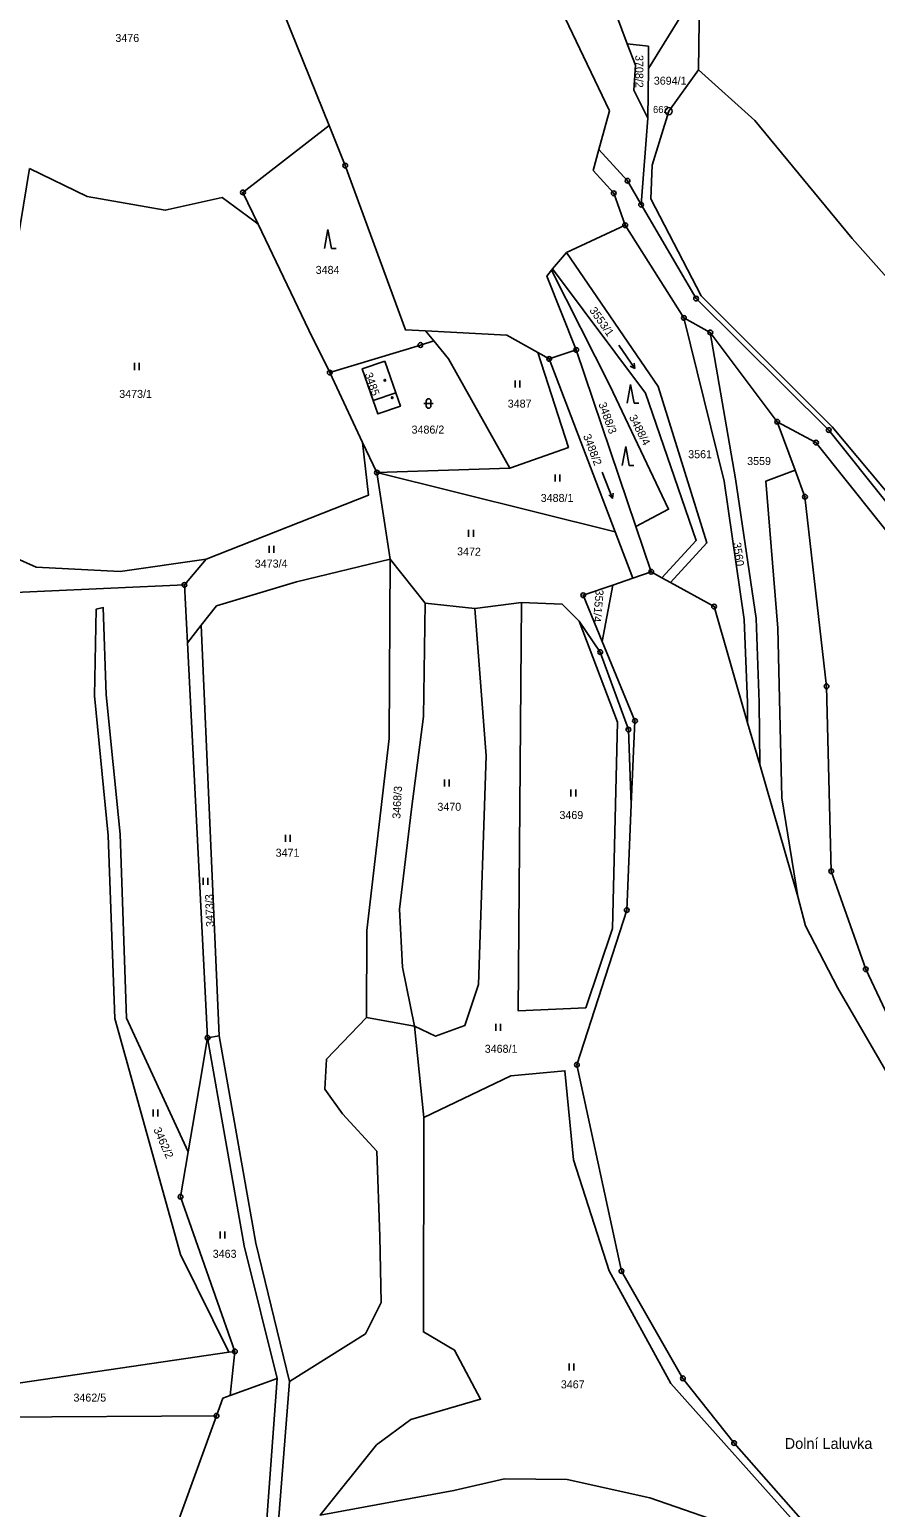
# Model space of a CAD drawing. Extents: x -644096 to -634268, y -1141430 to -1133463.
# Drawn here: x -641546.1 to -641366.3, y -1138053 to -1137739 of the extents above; entities that cross this region are included whole.
import ezdxf

# ---------------------------------------------------------------- set-up
doc = ezdxf.new("R2010")
doc.units = 0
for name, color, linetype in [('_CIVIL_CONSTRUCTION', 7, 'Continuous'), ('M_Svah_Nasyp', 7, 'Continuous'), ('M_Svah_Zarez', 7, 'Continuous'), ('svrsek_osa_sjezdy', 7, 'Continuous'), ('svrsek_osa_VRT', 7, 'Continuous'), ('svrsek_popisy_VRT', 7, 'Continuous'), ('terminal_VRT', 7, 'Continuous')]:
    doc.layers.add(name, color=color, linetype=linetype)

msp = doc.modelspace()

# ---------------------------------------------------------------- linework, layer by layer
at = {"layer": '_CIVIL_CONSTRUCTION'}
for centre, radius in [((-641410.28, -1137756.33), 0.75), ((-641410.28, -1137756.33), 0.03), ((-641479.03, -1137767.88), 0.5), ((-641479.03, -1137767.88), 0.0303), ((-641419.02, -1137771.11), 0.5), ((-641419.02, -1137771.11), 0.0303), ((-641500.77, -1137773.59), 0.5), ((-641500.77, -1137773.59), 0.0303), ((-641421.97, -1137773.78), 0.5), ((-641421.97, -1137773.78), 0.0303), ((-641416.17, -1137776.19), 0.5), ((-641416.17, -1137776.19), 0.0303), ((-641419.54, -1137780.55), 0.5), ((-641419.54, -1137780.55), 0.0303), ((-641404.46, -1137796.15), 0.5), ((-641404.46, -1137796.15), 0.0303), ((-641407.05, -1137800.25), 0.5), ((-641407.05, -1137800.25), 0.0303), ((-641401.44, -1137803.34), 0.5), ((-641401.44, -1137803.34), 0.0303), ((-641463.05, -1137806.01), 0.5), ((-641463.05, -1137806.01), 0.0303), ((-641429.94, -1137807.04), 0.5), ((-641435.67, -1137808.96), 0.5), ((-641435.67, -1137808.96), 0.0303), ((-641429.94, -1137807.04), 0.0303), ((-641482.33, -1137811.86), 0.5), ((-641482.33, -1137811.86), 0.0303), ((-641387.22, -1137822.31), 0.5), ((-641387.22, -1137822.31), 0.0303), ((-641376.27, -1137824.09), 0.5), ((-641376.27, -1137824.09), 0.0303), ((-641378.98, -1137826.73), 0.5), ((-641378.98, -1137826.73), 0.0303), ((-641472.29, -1137833.12), 0.5), ((-641472.29, -1137833.12), 0.0303), ((-641381.32, -1137838.24), 0.5), ((-641381.32, -1137838.24), 0.0303), ((-641414.01, -1137854.19), 0.5), ((-641513.21, -1137856.99), 0.5), ((-641513.21, -1137856.99), 0.0303), ((-641414.01, -1137854.19), 0.0303), ((-641428.45, -1137859.18), 0.5), ((-641428.45, -1137859.18), 0.0303), ((-641400.64, -1137861.57), 0.5), ((-641400.64, -1137861.57), 0.0303), ((-641424.83, -1137871.24), 0.5), ((-641424.83, -1137871.24), 0.0303), ((-641376.74, -1137878.53), 0.5), ((-641376.74, -1137878.53), 0.0303), ((-641417.45, -1137885.88), 0.5), ((-641418.85, -1137887.73), 0.5), ((-641418.85, -1137887.73), 0.0303), ((-641417.45, -1137885.88), 0.0303), ((-641375.73, -1137917.82), 0.5), ((-641375.73, -1137917.82), 0.0303), ((-641419.21, -1137926.07), 0.5), ((-641419.21, -1137926.07), 0.0303), ((-641368.41, -1137938.64), 0.5), ((-641368.41, -1137938.64), 0.0303), ((-641508.28, -1137953.19), 0.5), ((-641508.28, -1137953.19), 0.0303), ((-641429.79, -1137958.93), 0.5), ((-641429.79, -1137958.93), 0.0303), ((-641514.04, -1137986.99), 0.5), ((-641514.04, -1137986.99), 0.0303), ((-641420.33, -1138002.78), 0.5), ((-641420.33, -1138002.78), 0.0303), ((-641502.49, -1138019.84), 0.5), ((-641502.49, -1138019.84), 0.0303), ((-641407.28, -1138025.56), 0.5), ((-641407.28, -1138025.56), 0.0303), ((-641506.38, -1138033.52), 0.5), ((-641506.38, -1138033.52), 0.0303), ((-641396.39, -1138039.31), 0.5), ((-641396.39, -1138039.31), 0.0303)]:
    msp.add_circle(centre, radius, dxfattribs=at)
at = {"layer": 'M_Svah_Nasyp'}
msp.add_line((-641473.08, -1137817.79), (-641468.29, -1137816.14), dxfattribs=at)
at = {"layer": 'M_Svah_Zarez'}
for centre in [(-641470.61, -1137813.5), (-641469.05, -1137817.2)]:
    msp.add_circle(centre, 0.175, dxfattribs=at)
at = {"layer": 'svrsek_osa_sjezdy'}
for p, q in [((-641482.73, -1137781.48), (-641483.48, -1137785.48)), ((-641481.98, -1137785.48), (-641482.73, -1137781.48)), ((-641481.98, -1137785.48), (-641480.98, -1137785.48)), ((-641420.92, -1137806.07), (-641417.48, -1137810.99)), ((-641523.81, -1137811.32), (-641523.81, -1137809.82)), ((-641522.81, -1137811.32), (-641522.81, -1137809.82)), ((-641417.48, -1137810.99), (-641417.63, -1137809.9)), ((-641417.48, -1137810.99), (-641418.45, -1137810.47)), ((-641442.91, -1137815.04), (-641442.91, -1137813.54)), ((-641441.91, -1137815.04), (-641441.91, -1137813.54)), ((-641418.4, -1137814.39), (-641419.15, -1137818.39)), ((-641417.65, -1137818.39), (-641418.4, -1137814.39)), ((-641462.33, -1137818.44), (-641460.33, -1137818.44)), ((-641461.83, -1137817.94), (-641461.83, -1137818.94)), ((-641460.83, -1137818.94), (-641460.83, -1137817.94)), ((-641417.65, -1137818.39), (-641416.65, -1137818.39)), ((-641419.42, -1137827.6), (-641420.17, -1137831.6)), ((-641418.67, -1137831.6), (-641419.42, -1137827.6)), ((-641418.67, -1137831.6), (-641417.67, -1137831.6)), ((-641434.44, -1137835), (-641434.44, -1137833.5)), ((-641433.44, -1137835), (-641433.44, -1137833.5)), ((-641424.45, -1137833.03), (-641422.21, -1137838.59)), ((-641422.21, -1137838.59), (-641423.04, -1137837.87)), ((-641422.21, -1137838.59), (-641422.11, -1137837.5)), ((-641452.81, -1137846.75), (-641452.81, -1137845.25)), ((-641451.81, -1137846.75), (-641451.81, -1137845.25)), ((-641495.2, -1137850.18), (-641495.2, -1137848.68)), ((-641494.2, -1137850.18), (-641494.2, -1137848.68)), ((-641457.96, -1137899.84), (-641457.96, -1137898.34)), ((-641456.96, -1137899.84), (-641456.96, -1137898.34)), ((-641431.06, -1137901.95), (-641431.06, -1137900.45)), ((-641430.06, -1137901.95), (-641430.06, -1137900.45)), ((-641491.72, -1137911.6), (-641491.72, -1137910.1)), ((-641490.72, -1137911.6), (-641490.72, -1137910.1)), ((-641509.23, -1137920.71), (-641509.23, -1137919.21)), ((-641508.23, -1137920.71), (-641508.23, -1137919.21)), ((-641447.02, -1137951.76), (-641447.02, -1137950.26)), ((-641446.02, -1137951.76), (-641446.02, -1137950.26)), ((-641519.86, -1137969.95), (-641519.86, -1137968.45)), ((-641518.86, -1137969.95), (-641518.86, -1137968.45)), ((-641505.61, -1137995.88), (-641505.61, -1137994.38)), ((-641504.61, -1137995.88), (-641504.61, -1137994.38)), ((-641431.42, -1138023.92), (-641431.42, -1138022.42)), ((-641430.42, -1138023.92), (-641430.42, -1138022.42))]:
    msp.add_line(p, q, dxfattribs=at)
for centre, start, end in [((-641461.33, -1137817.94), 0, 180), ((-641461.33, -1137818.94), 180, 359.9879)]:
    msp.add_arc(centre, 0.5, start, end, dxfattribs=at)
at = {"layer": 'terminal_VRT'}
for p, q in [((-641482.45, -1137759.38), (-641495.91, -1137725.95)), ((-641403.67, -1137729.6), (-641414.58, -1137747.28)), ((-641403.97, -1137747.54), (-641403.67, -1137729.6)), ((-641414.58, -1137747.28), (-641414.72, -1137757.83)), ((-641414.72, -1137757.83), (-641416.17, -1137776.19)), ((-641419.54, -1137780.55), (-641431.98, -1137786.38)), ((-641419.54, -1137780.55), (-641407.05, -1137800.25)), ((-641431.98, -1137786.38), (-641434.95, -1137789.83)), ((-641412.55, -1137814.85), (-641431.98, -1137786.38)), ((-641434.95, -1137789.83), (-641435.18, -1137790.11)), ((-641407.05, -1137800.25), (-641401.44, -1137803.34)), ((-641460.23, -1137805.15), (-641462, -1137803.01)), ((-641401.44, -1137803.34), (-641387.22, -1137822.31)), ((-641435.67, -1137808.96), (-641438.1, -1137807.6)), ((-641429.94, -1137807.04), (-641435.67, -1137808.96)), ((-641421.65, -1137845.7), (-641435.67, -1137808.96)), ((-641417.26, -1137844.56), (-641429.94, -1137807.04)), ((-641475.35, -1137826.72), (-641482.33, -1137811.86)), ((-641383.41, -1137832.6), (-641387.22, -1137822.31)), ((-641475.35, -1137826.72), (-641472.29, -1137833.12)), ((-641472.29, -1137833.12), (-641444.08, -1137832.16)), ((-641421.65, -1137845.7), (-641472.29, -1137833.12)), ((-641472.29, -1137833.12), (-641469.47, -1137851.53)), ((-641414.01, -1137854.19), (-641417.26, -1137844.56)), ((-641417.9, -1137855.54), (-641421.65, -1137845.7)), ((-641508.61, -1137851.53), (-641513.21, -1137856.99)), ((-641462.06, -1137860.84), (-641469.47, -1137851.53)), ((-641512.58, -1137869.26), (-641513.21, -1137856.99)), ((-641424.41, -1137868.99), (-641422.18, -1137857.02)), ((-641422.18, -1137857.02), (-641417.9, -1137855.54)), ((-641417.9, -1137855.54), (-641414.01, -1137854.19)), ((-641414.01, -1137854.19), (-641411.73, -1137855.45)), ((-641411.73, -1137855.45), (-641409.92, -1137856.45)), ((-641451.48, -1137861.98), (-641462.06, -1137860.84)), ((-641441.58, -1137860.7), (-641451.48, -1137861.98)), ((-641509.63, -1137865.54), (-641512.58, -1137869.26)), ((-641509.63, -1137865.54), (-641505.82, -1137952.76)), ((-641508.28, -1137953.19), (-641512.58, -1137869.26)), ((-641393.51, -1137886.26), (-641390.95, -1137895.12)), ((-641390.95, -1137895.12), (-641382.86, -1137923.16)), ((-641464.35, -1137950.73), (-641474.51, -1137948.89)), ((-641462.33, -1137970.13), (-641464.35, -1137950.73)), ((-641505.82, -1137952.76), (-641508.28, -1137953.19)), ((-641503.78, -1138020.02), (-641502.49, -1138019.84)), ((-641503.48, -1138029.21), (-641502.49, -1138019.84)), ((-641493.5, -1138025.57), (-641503.48, -1138029.21)), ((-641506.38, -1138033.52), (-641595.89, -1138034.03))]:
    msp.add_line(p, q, dxfattribs=at)
for points in [[(-641425.11, -1137764.49), (-641422.86, -1137756.22), (-641456.68, -1137685.58), (-641495.74, -1137612.44), (-641501.22, -1137583.22), (-641506.04, -1137580.52), (-641511.42, -1137577.68)], [(-641419.09, -1137742.01), (-641428.9, -1137715.68), (-641445.3, -1137689.82), (-641463.81, -1137649.83), (-641469.75, -1137633.68)], [(-641414.72, -1137757.83), (-641417.69, -1137751.87), (-641417.32, -1137746.58), (-641419.09, -1137742.01)], [(-641419.09, -1137742.01), (-641414.59, -1137742.53), (-641414.58, -1137747.28)], [(-641403.97, -1137747.54), (-641410.28, -1137756.33), (-641413.83, -1137767.83), (-641414.09, -1137774.97), (-641403.42, -1137795.54), (-641375.56, -1137823.38), (-641348.59, -1137855.53), (-641324.75, -1137879.5), (-641325.44, -1137880.23)], [(-641314.16, -1137848.09), (-641339.44, -1137819.2), (-641371.31, -1137783.36), (-641392.01, -1137758.33), (-641403.97, -1137747.54)], [(-641497.56, -1137780.31), (-641500.77, -1137773.59), (-641482.45, -1137759.38)], [(-641462, -1137803.01), (-641466.23, -1137802.79), (-641479.03, -1137767.88), (-641482.45, -1137759.38)], [(-641425.11, -1137764.49), (-641426.33, -1137768.95), (-641421.97, -1137773.78), (-641419.54, -1137780.55)], [(-641416.17, -1137776.19), (-641419.02, -1137771.11), (-641425.11, -1137764.49)], [(-641546.15, -1137768.53), (-641559.05, -1137846.83), (-641544.72, -1137853.19), (-641526.86, -1137854.13), (-641508.61, -1137851.53)], [(-641497.56, -1137780.31), (-641498.49, -1137779.62), (-641505.2, -1137774.68), (-641517.3, -1137777.37), (-641533.87, -1137774.42), (-641546.15, -1137768.53)], [(-641325.44, -1137880.23), (-641350.07, -1137856.89), (-641376.27, -1137824.09), (-641404.46, -1137796.15), (-641416.17, -1137776.19)], [(-641482.33, -1137811.86), (-641486.78, -1137802.83), (-641497.56, -1137780.31)], [(-641435.18, -1137790.11), (-641436.17, -1137791.36), (-641429.94, -1137807.04)], [(-641417.26, -1137844.56), (-641410.32, -1137840.91), (-641422.79, -1137814.6), (-641435.18, -1137790.11)], [(-641411.73, -1137855.45), (-641404.43, -1137847.57), (-641415.22, -1137816.27), (-641434.95, -1137789.83)], [(-641407.05, -1137800.25), (-641398.52, -1137834.94), (-641394.22, -1137864.36), (-641393.54, -1137881.99), (-641393.51, -1137886.26)], [(-641438.1, -1137807.6), (-641444.69, -1137803.93), (-641462, -1137803.01)], [(-641401.44, -1137803.34), (-641396.06, -1137834.46), (-641391.73, -1137864.13), (-641391.04, -1137881.93), (-641390.95, -1137895.12)], [(-641482.33, -1137811.86), (-641463.05, -1137806.01), (-641460.23, -1137805.15)], [(-641444.08, -1137832.16), (-641457.08, -1137808.96), (-641460.23, -1137805.15)], [(-641470.6, -1137809.41), (-641475.41, -1137811.04), (-641473.08, -1137817.79), (-641472.1, -1137820.64), (-641467.31, -1137818.99), (-641468.29, -1137816.14), (-641470.6, -1137809.41)], [(-641444.08, -1137832.16), (-641431.59, -1137827.76), (-641438.1, -1137807.6)], [(-641409.92, -1137856.45), (-641402.15, -1137848.05), (-641412.55, -1137814.85)], [(-641387.22, -1137822.31), (-641378.98, -1137826.73), (-641352.66, -1137859.72), (-641333.71, -1137878.21), (-641324, -1137888.22)], [(-641508.61, -1137851.53), (-641474.08, -1137837.89), (-641475.35, -1137826.72)], [(-641383.41, -1137832.6), (-641389.64, -1137834.93), (-641387.1, -1137866.2), (-641386.26, -1137902.21), (-641382.86, -1137923.16)], [(-641351.26, -1137964.87), (-641363.09, -1137949.85), (-641368.41, -1137938.64), (-641375.73, -1137917.82), (-641376.74, -1137878.53), (-641381.32, -1137838.24), (-641383.41, -1137832.6)], [(-641469.47, -1137851.53), (-641489.39, -1137856.34), (-641506.38, -1137861.44), (-641509.63, -1137865.54)], [(-641469.47, -1137851.53), (-641469.68, -1137889.61), (-641474.47, -1137930.44), (-641474.51, -1137948.89)], [(-641513.21, -1137856.99), (-641560.23, -1137859.08), (-641572.97, -1137858.51)], [(-641424.41, -1137868.99), (-641428.45, -1137859.18), (-641422.18, -1137857.02)], [(-641409.92, -1137856.45), (-641400.64, -1137861.57), (-641393.51, -1137886.26)], [(-641512.41, -1137977.43), (-641525.53, -1137949.04), (-641526.9, -1137909.94), (-641529.85, -1137880.33), (-641530.47, -1137861.81), (-641531.98, -1137862.16), (-641532.34, -1137880.58), (-641529.39, -1137910.19), (-641528.03, -1137949.13), (-641514.07, -1137999.24), (-641503.78, -1138020.02)], [(-641464.35, -1137950.73), (-641466.89, -1137938.19), (-641467.53, -1137925.88), (-641464.92, -1137904.66), (-641462.43, -1137884.93), (-641462.06, -1137860.84)], [(-641451.48, -1137861.98), (-641449.1, -1137893.33), (-641450.74, -1137941.89), (-641453.61, -1137950.61), (-641459.87, -1137952.86), (-641464.35, -1137950.73)], [(-641429.34, -1137864.65), (-641421.15, -1137886.15), (-641422.23, -1137929.97), (-641427.93, -1137946.83), (-641442.3, -1137947.47), (-641441.58, -1137860.7)], [(-641429.34, -1137864.65), (-641432.96, -1137861.07), (-641441.58, -1137860.7)], [(-641418.23, -1137903.63), (-641418.85, -1137887.73), (-641424.83, -1137871.24), (-641429.34, -1137864.65)], [(-641418.23, -1137903.63), (-641417.45, -1137885.88), (-641424.41, -1137868.99)], [(-641373.85, -1138064.88), (-641396.39, -1138039.31), (-641407.28, -1138025.56), (-641420.33, -1138002.78), (-641429.79, -1137958.93), (-641419.21, -1137926.07), (-641418.23, -1137903.63)], [(-641382.86, -1137923.16), (-641381.18, -1137929.41), (-641374.33, -1137942.68), (-641355.72, -1137974.76), (-641320.69, -1137998.81), (-641248.56, -1138012.71)], [(-641474.51, -1137948.89), (-641483.04, -1137957.75), (-641483.4, -1137964.13), (-641479.62, -1137969.33), (-641472.34, -1137977.31), (-641471.66, -1137995.44), (-641471.38, -1138009.48), (-641474.72, -1138016.1), (-641490.88, -1138026.24)], [(-641512.41, -1137977.43), (-641510.08, -1137963.74), (-641508.28, -1137953.19)], [(-641493.5, -1138025.57), (-641500.51, -1137997.38), (-641508.28, -1137953.19)], [(-641490.88, -1138026.24), (-641498.06, -1137996.85), (-641505.82, -1137952.76)], [(-641373.85, -1138064.88), (-641381.96, -1138057.82), (-641409.8, -1138026.63), (-641422.93, -1138002.74), (-641430.51, -1137979.16), (-641432.33, -1137960.22), (-641443.82, -1137961.29), (-641462.33, -1137970.13)], [(-641370.69, -1138086.45), (-641384.8, -1138065.03), (-641394.24, -1138057.89), (-641414.27, -1138050.93), (-641431.86, -1138047.07), (-641445.19, -1138046.92), (-641455.94, -1138049.41), (-641484.39, -1138054.62), (-641472.41, -1138039.72), (-641465.08, -1138034.31), (-641450.28, -1138030), (-641455.8, -1138019.55), (-641462.41, -1138015.68), (-641462.33, -1137970.13)], [(-641502.49, -1138019.84), (-641514.04, -1137986.99), (-641512.41, -1137977.43)], [(-641595.89, -1138034.03), (-641556.35, -1138027.37), (-641554.85, -1138027.5), (-641503.78, -1138020.02)], [(-641378.25, -1138084.34), (-641385.85, -1138082.21), (-641419.6, -1138072.79), (-641485.59, -1138065.55), (-641493.32, -1138062.69), (-641495.98, -1138059.38), (-641493.5, -1138025.57)], [(-641378.25, -1138084.34), (-641395.46, -1138072.42), (-641485.01, -1138063.1), (-641491.8, -1138060.59), (-641493.41, -1138058.58), (-641490.88, -1138026.24)], [(-641503.48, -1138029.21), (-641505.02, -1138029.78), (-641506.38, -1138033.52)], [(-641506.38, -1138033.52), (-641514.19, -1138054.98), (-641511, -1138065.92), (-641499.25, -1138078.39), (-641497.55, -1138082.01), (-641499.97, -1138099.24)]]:
    msp.add_lwpolyline(points, dxfattribs=at)

# ---------------------------------------------------------------- texts
at = {"layer": '_CIVIL_CONSTRUCTION'}
msp.add_text('662', height=1.5, dxfattribs=at).set_placement((-641413.62, -1137756.71))
at = {"layer": 'svrsek_osa_VRT'}
for s, p in [('3476', (-641527.89, -1137741.62)), ('3694/1', (-641413.45, -1137750.7)), ('3484', (-641485.32, -1137790.9)), ('3473/1', (-641527.07, -1137817.25)), ('3487', (-641444.5, -1137819.31)), ('3486/2', (-641464.94, -1137824.83)), ('3561', (-641406.14, -1137830.06)), ('3559', (-641393.61, -1137831.51)), ('3488/1', (-641437.49, -1137839.35)), ('3473/4', (-641498.26, -1137853.3)), ('3470', (-641459.45, -1137904.97)), ('3469', (-641433.51, -1137906.72)), ('3471', (-641493.83, -1137914.73)), ('3468/1', (-641449.39, -1137956.39)), ('3463', (-641507.2, -1137999.95)), ('3467', (-641433.21, -1138027.69)), ('3462/5', (-641536.8, -1138030.5))]:
    msp.add_text(s, height=1.7, dxfattribs=at).set_placement(p)
for s, rotation, p in [('3708/2', 270, (-641417.38, -1137744.4)), ('3553/1', 305, (-641427.22, -1137798.66)), ('3485', 289, (-641474.93, -1137812.19)), ('3488/3', 290, (-641425.25, -1137818.53)), ('3488/4', 297, (-641418.78, -1137821.34)), ('3488/2', 291, (-641428.52, -1137825.31)), ('3472', 359, (-641455.28, -1137850.7)), ('3560', 278, (-641396.61, -1137848.08)), ('3551/4', 265, (-641425.78, -1137857.89)), ('3468/3', 87, (-641467.33, -1137906.7)), ('3473/3', 92, (-641506.9, -1137929.62)), ('3462/2', 294, (-641519.85, -1137972.68))]:
    msp.add_text(s, height=1.7, rotation=rotation, dxfattribs=at).set_placement(p)
at = {"layer": 'svrsek_popisy_VRT'}
msp.add_text('Dolní Laluvka', height=2.3, dxfattribs=at).set_placement((-641385.63, -1138040.55))

doc.saveas('drawing.dxf')
